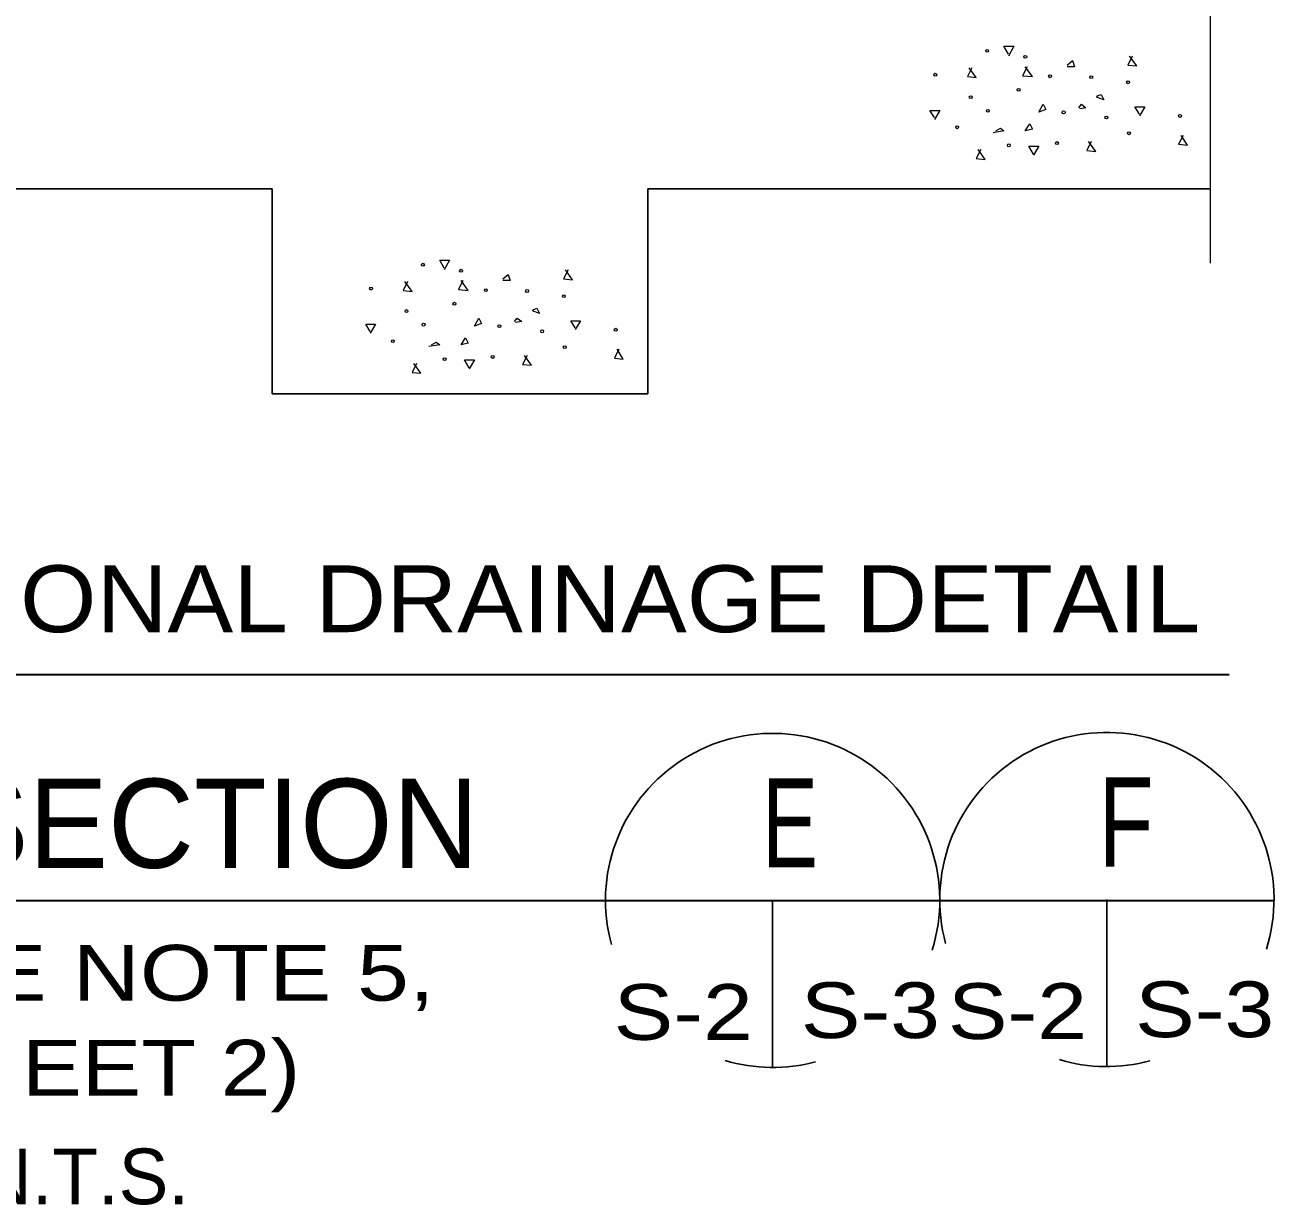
# Model space of a CAD drawing. Extents: x -28.1 to 13.9, y -16.1 to 13.9.
# Drawn here: x 2.598 to 5.4, y -6.999 to -4.35 of the extents above; entities that cross this region are included whole.
import ezdxf
from ezdxf.enums import TextEntityAlignment as Align

# ---------------------------------------------------------------- set-up
doc = ezdxf.new("R2010")
doc.units = 0
doc.header["$LTSCALE"] = 0.05
doc.layers.add('1', color=7, linetype='Continuous', lineweight=13)
doc.layers.add('2', color=7, linetype='Continuous', lineweight=13)

msp = doc.modelspace()

# ---------------------------------------------------------------- linework, layer by layer
at = {"layer": '1'}
msp.add_line((5.25696, -4.20031), (5.25696, -4.88531), dxfattribs=at)
at = {"layer": '1', "lineweight": 25}
for p, q in [((1.92496, -4.71831), (3.15196, -4.71831)), ((3.15196, -5.17831), (3.15196, -4.71831)), ((3.99496, -4.71831), (5.25596, -4.71831)), ((3.99496, -5.17831), (3.99496, -4.71831)), ((3.15196, -5.17831), (3.99496, -5.17831)), ((4.27496, -6.31531), (4.27496, -6.69031)), ((5.02496, -6.31331), (5.02496, -6.68831))]:
    msp.add_line(p, q, dxfattribs=at)
at = {"layer": '1', "lineweight": 35}
for p, q in [((1.89796, -5.80831), (5.29896, -5.80831)), ((1.65096, -6.31531), (5.39896, -6.31531))]:
    msp.add_line(p, q, dxfattribs=at)
at = {"layer": '1', "lineweight": 25}
for centre, start, end in [((4.27496, -6.31531), 342.70891, 195.26862), ((5.02496, -6.31331), 342.70891, 195.26862), ((4.27496, -6.31531), 253.4742, 284.92162), ((5.02496, -6.31331), 253.4742, 284.92162)]:
    msp.add_arc(centre, 0.375, start, end, dxfattribs=at)
at = {"layer": '2'}
for p, q in [((4.93596, -4.44031), (4.94796, -4.43031)), ((3.66996, -4.92031), (3.68196, -4.91031))]:
    msp.add_line(p, q, dxfattribs=at)
for points in [[(4.80396, -4.41631), (4.79396, -4.39831), (4.81596, -4.39831), (4.80396, -4.42031)], [(5.08196, -4.42031), (5.07196, -4.44031), (5.09196, -4.44231), (5.07596, -4.42031)], [(4.72196, -4.44631), (4.71196, -4.46631), (4.73196, -4.46831), (4.71596, -4.44631)], [(4.84596, -4.44431), (4.83596, -4.46431), (4.85796, -4.46631), (4.84196, -4.44431)], [(4.94796, -4.43031), (4.95196, -4.44431), (4.93596, -4.44431)], [(5.00196, -4.51031), (5.01196, -4.50631), (5.01796, -4.51831), (5.00196, -4.51231)], [(4.96196, -4.53631), (4.96796, -4.52831), (4.97796, -4.53631), (4.96396, -4.53831)], [(5.09796, -4.55031), (5.08796, -4.53431), (5.10996, -4.53431), (5.09796, -4.55431)], [(4.63796, -4.55831), (4.62796, -4.54231), (4.64996, -4.54231), (4.63796, -4.56231)], [(4.77596, -4.58831), (4.78596, -4.58231), (4.79396, -4.58831), (4.76996, -4.59231)], [(4.85996, -4.64031), (4.84996, -4.62231), (4.87196, -4.62231), (4.85996, -4.64231)], [(4.98996, -4.61231), (4.97996, -4.63231), (4.99996, -4.63431), (4.98396, -4.61231)], [(5.19596, -4.59831), (5.18596, -4.61831), (5.20596, -4.62031), (5.19196, -4.59831)], [(4.74196, -4.63031), (4.73196, -4.65031), (4.75196, -4.65231), (4.73596, -4.63031)], [(3.53796, -4.89631), (3.52796, -4.87831), (3.54996, -4.87831), (3.53796, -4.90031)], [(3.81596, -4.90031), (3.80596, -4.92031), (3.82596, -4.92231), (3.80996, -4.90031)], [(3.45596, -4.92631), (3.44596, -4.94631), (3.46596, -4.94831), (3.44996, -4.92631)], [(3.57996, -4.92431), (3.56996, -4.94431), (3.59196, -4.94631), (3.57596, -4.92431)], [(3.68196, -4.91031), (3.68596, -4.92431), (3.66996, -4.92431)], [(3.73596, -4.99031), (3.74596, -4.98631), (3.75196, -4.99831), (3.73596, -4.99231)], [(3.69596, -5.01631), (3.70196, -5.00831), (3.71196, -5.01631), (3.69796, -5.01831)], [(3.83196, -5.03031), (3.82196, -5.01431), (3.84396, -5.01431), (3.83196, -5.03431)], [(3.37196, -5.03831), (3.36196, -5.02231), (3.38396, -5.02231), (3.37196, -5.04231)], [(3.50996, -5.06831), (3.51996, -5.06231), (3.52796, -5.06831), (3.50396, -5.07231)], [(3.72396, -5.09231), (3.71396, -5.11231), (3.73396, -5.11431), (3.71796, -5.09231)], [(3.92996, -5.07831), (3.91996, -5.09831), (3.93996, -5.10031), (3.92596, -5.07831)], [(3.47596, -5.11031), (3.46596, -5.13031), (3.48596, -5.13231), (3.46996, -5.11031)], [(3.59396, -5.12031), (3.58396, -5.10231), (3.60596, -5.10231), (3.59396, -5.12231)]]:
    msp.add_lwpolyline(points, dxfattribs=at)
for points in [[(4.87196, -4.54631), (4.88196, -4.52831), (4.88796, -4.54031)], [(4.84196, -4.58831), (4.85196, -4.57231), (4.85796, -4.58431)], [(3.60596, -5.02631), (3.61596, -5.00831), (3.62196, -5.02031)], [(3.57596, -5.06831), (3.58596, -5.05231), (3.59196, -5.06431)]]:
    msp.add_lwpolyline(points, close=True, dxfattribs=at)
for centre in [(4.75646, -4.40856), (4.84196, -4.42206), (4.63996, -4.46206), (4.89746, -4.46556), (4.98996, -4.46756), (5.07246, -4.47906), (4.71946, -4.51256), (4.82696, -4.49606), (4.75796, -4.54306), (4.92796, -4.54656), (5.02396, -4.55806), (5.18896, -4.55456), (4.68896, -4.58006), (5.07446, -4.59356), (4.80496, -4.62056), (4.91296, -4.61556), (3.49046, -4.88856), (3.57596, -4.90206), (3.37396, -4.94206), (3.63146, -4.94556), (3.72396, -4.94756), (3.80646, -4.95906), (3.56096, -4.97606), (3.45346, -4.99256), (3.49196, -5.02306), (3.66196, -5.02656), (3.75796, -5.03806), (3.92296, -5.03456), (3.42296, -5.06006), (3.80846, -5.07356), (3.53896, -5.10056), (3.64696, -5.09556)]:
    msp.add_circle(centre, 0.00325, dxfattribs=at)

# ---------------------------------------------------------------- texts
at = {"layer": '1'}
for s, height, width, p in [('OPTIONAL DRAINAGE DETAIL', 0.15, 1.1, (3.65313, -5.71331)), ('E', 0.2, 0.7, (4.3141, -6.24131)), ('F', 0.2, 0.75, (5.0681, -6.23931)), ('(SEE NOTE 5,', 0.125, 1.25, (2.8378, -6.54031)), ('S-2', 0.125, 1.2, (4.07432, -6.62831)), ('S-3', 0.125, 1.2, (4.49432, -6.62431)), ('S-2', 0.125, 1.2, (4.82432, -6.62631)), ('S-3', 0.125, 1.2, (5.24432, -6.62231)), ('SHEET 2)', 0.125, 1.2, (2.76377, -6.75331))]:
    msp.add_text(s, height=height, dxfattribs=dict(at, width=width)).set_placement(p, align=Align.CENTER)
for s, height, p in [('SECTION', 0.2, (3.02136, -6.24231)), ('N.T.S.', 0.125, (2.72882, -6.99731))]:
    msp.add_text(s, height=height, dxfattribs=at).set_placement(p, align=Align.CENTER)

doc.saveas('drawing.dxf')
